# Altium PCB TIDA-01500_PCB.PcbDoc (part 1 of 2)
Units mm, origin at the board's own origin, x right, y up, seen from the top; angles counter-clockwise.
Board outline 177.8 x 50.8 mm, 2 copper layers (Top Layer, Bottom Layer), stack 1.575 mm thick; 57 components, 28 nets, 152 pads, 175 vias.
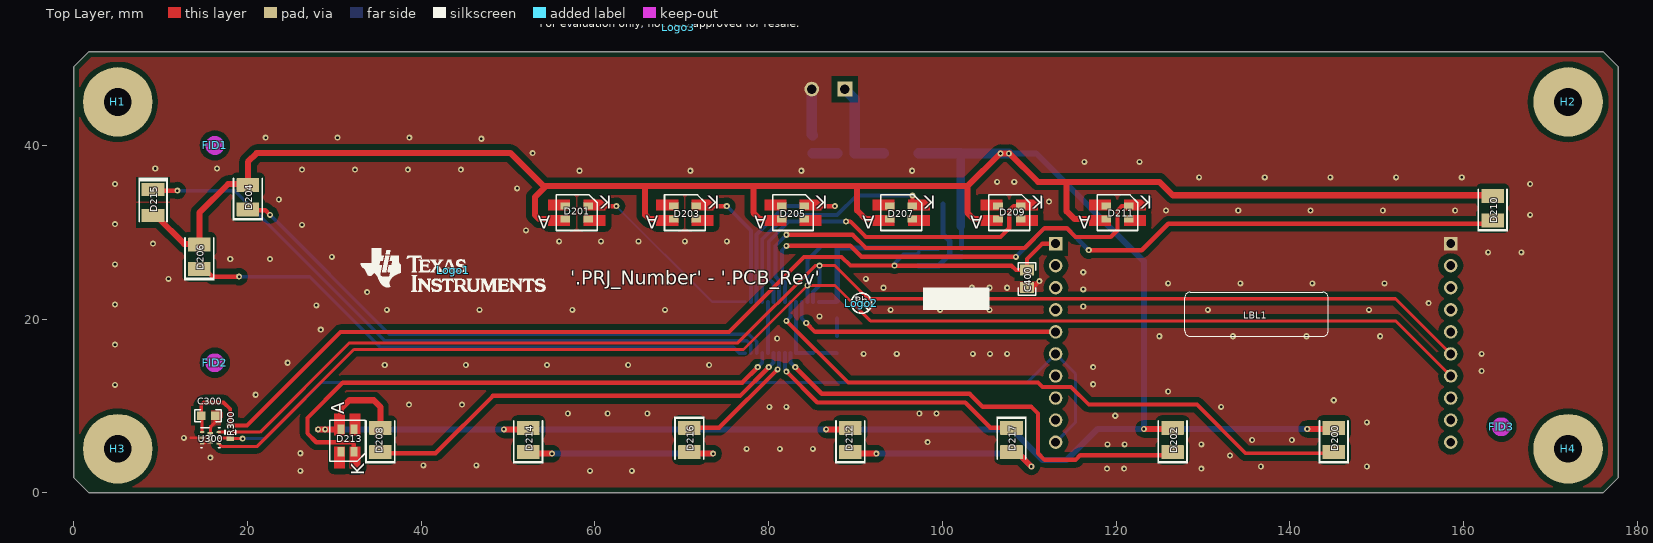
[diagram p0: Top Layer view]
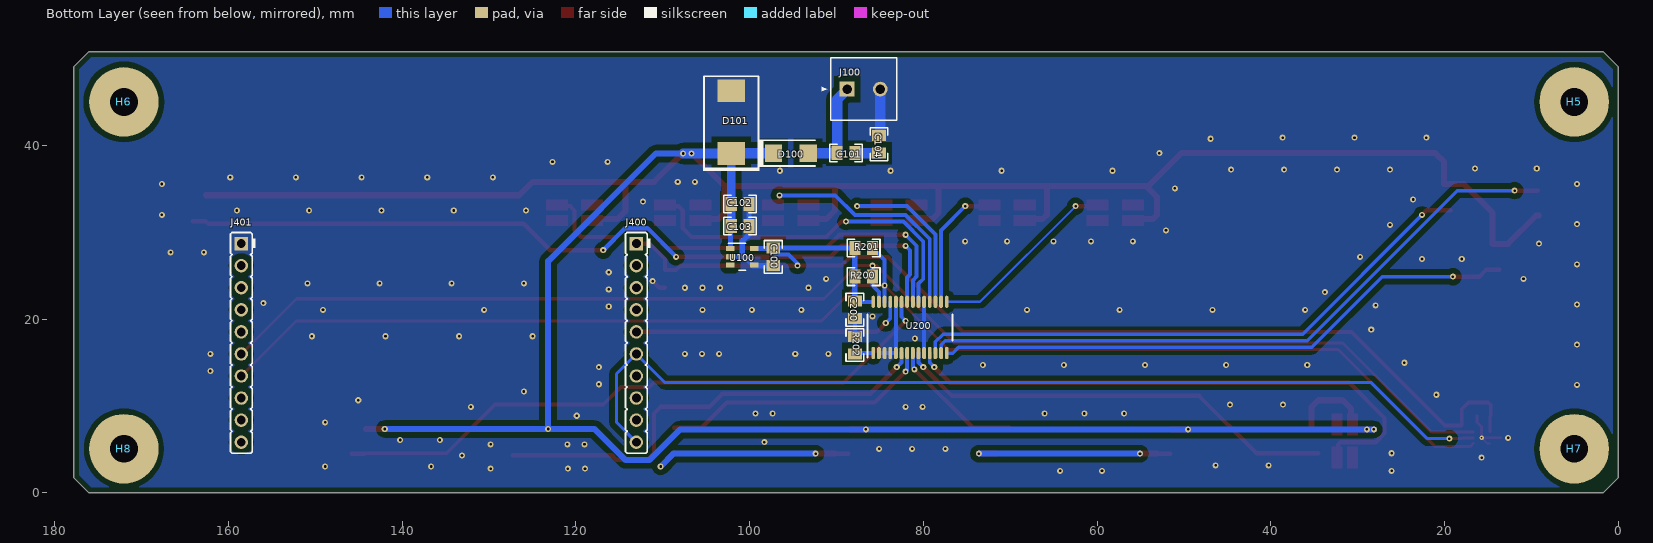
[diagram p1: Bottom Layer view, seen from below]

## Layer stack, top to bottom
Top Solder: solder mask 0.0102, Solder Resist, Dk 3.5
Top Layer: signal copper 0.0356
Dielectric1: core 1.5037, FR-4, Dk 4.8
Bottom Layer: signal copper 0.0356
Bottom Solder: solder mask 0.0102, Solder Resist, Dk 3.5

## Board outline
0,1.778 0,49.022 1.778,50.8 176.022,50.8 177.8,49.022 177.8,1.778 176.022,0 1.778,0

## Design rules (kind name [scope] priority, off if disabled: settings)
AcuteAngle [All] p1: minimum=4.50000000000000E+0001 checktracksonly=FALSE
AssemblyTestPointUsage [All] p1: valid=2
BoardOutlineClearance BoardOutlineClearance_MountingHoles [OnCopper and InComponentClass('Mounting Holes')] p1: gap=1.016 ignorepadtopadclearanceinfootprint=FALSE
BoardOutlineClearance BoardOutlineClearance_Poly [OnCopper and IsPoly] p2: gap=0.635 ignorepadtopadclearanceinfootprint=FALSE
BoardOutlineClearance [OnCopper and Not InComponentClass('Logo') and not InComponentClass('FiducialMark') and not InRegion(1000,500,4000,800) and not InPoly] p3: gap=1.905 ignorepadtopadclearanceinfootprint=FALSE
Clearance Clearance_Keepouts [((IsTrack Or IsArc) And Not InPoly) And IsFree and IsKeepOut vs ((IsTrack Or IsArc) And Not InPoly) And IsFree and IsKeepOut] p1: gap=0 ignorepadtopadclearanceinfootprint=FALSE
Clearance Clearance_Poly [InPolygon] p2: gap=0.635 ignorepadtopadclearanceinfootprint=FALSE except(0: Arc-Hole Track-Hole SMDPad-Hole THPad-Hole Via-Hole Fill-Hole Poly-Hole Region-Hole Text-Hole)
Clearance [All vs not InComponentClass('FiducialMark')] p3: gap=0.2 ignorepadtopadclearanceinfootprint=FALSE except(0: Arc-Hole Track-Hole SMDPad-Hole THPad-Hole Via-Hole Fill-Hole Poly-Hole Region-Hole Text-Hole)
ComponentClearance ComponentClearance_MountingHoles_FiducialMarks [InComponentClass('Mounting Holes') vs InComponentClass('FiducialMark')] p1: gap=1.27 collisioncheckmode=3 verticalgap=0.254 showdistances=FALSE
ComponentClearance ComponentClearance_Shunt [InComponentClass('Header') vs InComponentClass('Shunt')] p2: gap=0 collisioncheckmode=3 verticalgap=0 showdistances=FALSE
ComponentClearance ComponentClearance_Logo [InComponentClass('Logo')] p3: gap=1.27 collisioncheckmode=3 verticalgap=0.254 showdistances=FALSE
ComponentClearance ComponentClearance_ScrewToNut [(HasFootprint('NY PMS 440 0025 PH')) vs (HasFootprint('Keystone_1902C'))] p4: gap=0.127 collisioncheckmode=3 verticalgap=0.254 showdistances=FALSE
ComponentClearance ComponentClearance_MountingHoles [InComponentClass('Mounting Holes')] p5: gap=6.35 collisioncheckmode=3 verticalgap=2540 showdistances=FALSE
ComponentClearance ComponentClearance_SmallPassives [HasFootprint('0201*') or HasFootprint('0402*') or HasFootprint('0508') or HasFootprint('0603*') or HasFootprint('0612') or HasFootprint('0805*') or HasFootprint('0815*') or HasFootprint('0830*') or HasFootprint('1206*') or HasFootprint('1210*') or HasFootprint('1808*') or HasFootprint('1812*') or HasFootprint('1825*') or HasFootprint('2010*') or HasFootprint('2220*') or HasFootprint('2225*') or HasFootprint('2512*') or HasFootprint('2728*') or HasFootprint('3518*') vs HasFootprint('0201*') or HasFootprint('0402*') or HasFootprint('0508') or HasFootprint('0603*') or HasFootprint('0612') or HasFootprint('0805*') or HasFootprint('0815*') or HasFootprint('0830*') or HasFootprint('1206*') or HasFootprint('1210*') or HasFootprint('1808*') or HasFootprint('1812*') or HasFootprint('1825*') or HasFootprint('2010*') or HasFootprint('2220*') or HasFootprint('2225*') or HasFootprint('2512*') or HasFootprint('2728*') or HasFootprint('3518*')] p6: gap=0.38 collisioncheckmode=3 verticalgap=0.254 showdistances=FALSE
ComponentClearance ComponentClearance_THtoSMT [IsThruComponent vs IsSMTComponent] p7: gap=1.016 collisioncheckmode=3 verticalgap=0.762 showdistances=FALSE
ComponentClearance ComponentClearance_THtoTH [IsThruComponent vs IsThruComponent] p8: gap=0.762 collisioncheckmode=3 verticalgap=0.762 showdistances=FALSE
ComponentClearance [All] p9: gap=0.762 collisioncheckmode=3 verticalgap=0.254 showdistances=FALSE
DiffPairsRouting [All] p1: maxlimit=2.54 minlimit=0.254 mostfreqgap=0.254 toplayer_minwidth=0.381 toplayer_maxwidth=0.381 toplayer_prefwidth=0.381 bottomlayer_minwidth=0.381 bottomlayer_maxwidth=0.381 bottomlayer_prefwidth=0.381 maxuncoupledlength=25.4
FabricationTestPointUsage TestPointUsage [All] p1: valid=2 allowmultiple=FALSE
FabricationTestpoint Testpoint [All] p1: side=3 testpointundercomponent=TRUE minsize=1.016 maxsize=2.54 preferedsize=1.524 minholesize=0 maxholesize=1.016 preferedholesize=0.813 testpointgrid=0.025 allowsidetop=TRUE allowsidebottom=TRUE usegrid=TRUE gridtolerance=0
FanoutControl Fanout_LCC [IsLCC] p1: bgadir=Out bgaviamode=Centered fanoutstyle=Auto fanoutdirection=Alternating viagrid=0.025 // Fanout_LCC (Default Rule)
FanoutControl Fanout_BGA [IsBGA] p2: bgadir=Out bgaviamode=Centered fanoutstyle=Auto fanoutdirection=Alternating viagrid=0.025 // Fanout_BGA (Default Rule)
FanoutControl Fanout_Default [All] p4: bgadir=Out bgaviamode=Centered fanoutstyle=Auto fanoutdirection=Alternating viagrid=0.025 // Fanout_Default (Default Rule)
FanoutControl Fanout_Small [(CompPinCount < 5)] p5: bgadir=Out bgaviamode=Centered fanoutstyle=Auto fanoutdirection=OutThenIn viagrid=0.025 // Fanout_Small (Default Rule)
HoleSize [All] p1: absolutevalues=TRUE maxlimit=6.375 minlimit=0.2 maxpercent=80.000 minpercent=20.000
MinimumAnnularRing MinimumAnnularRing_ThermalPadVias [IsVia and InAnyComponent] p1 off: minimumring=0.15
MinimumAnnularRing [All] p2: minimumring=0.15
MinimumSolderMaskSliver MinimumSolderMaskSliver_Logo [InComponentClass('Logo') vs InComponentClass('Logo')] p1 off: minsoldermaskwidth=0.018
MinimumSolderMaskSliver [All] p2 off: minsoldermaskwidth=0.1
PlaneClearance [All] p1: clearance=0.5
PlaneConnect [All] p1: planeconnectstyle=Relief reliefexpansion=0.254 reliefentries=4 reliefconductorwidth=0.254 reliefairgap=0.254
PolygonConnect [All] p1: connectstyle=Direct reliefconductorwidth=0.254 reliefentries=4 polygonreliefangle="90 Angle" airgapwidth=0.254
RoutingVias ThermalPadVias [IsVia and InAnyComponent] p1: holewidth=0.2 width=0.5 viastyle="Through Hole" minholewidth=0.2 minwidth=0.5 maxholewidth=0.4 maxwidth=0.8
RoutingVias [All] p2: holewidth=0.406 width=0.864 viastyle="Through Hole" minholewidth=0.2 minwidth=0.66 maxholewidth=1.016 maxwidth=1.651
ShortCircuit ShortCircuit_1 [HasFootprint('LED_PowerTOPLED_GF')] p1: allowed=TRUE
ShortCircuit [All] p2: allowed=FALSE
SilkToBoardRegionClearance [Not ((IsComment or IsDesignator) And (Hide <> 'False')) and not InRegion(1000,500,4000,800)] p1:
SilkToSilkClearance SilkToSilkClearance_Pb-FreeLogo [(HasFootprint('Pb-Free_Overlay_Medium') OR HasFootprint('Pb-Free_Overlay_Small')) vs (HasFootprint('Pb-Free_Overlay_Medium') OR HasFootprint('Pb-Free_Overlay_Small'))] p1 off: silktosilkclearance=0
SilkToSilkClearance [All] p2 off: silktosilkclearance=0.102
SilkToSolderMaskClearance SilkToComponentPadClearance [(IsPad or IsFill or IsRegion) and InAnycomponent] p1 off: minsilkscreentomaskgap=0.127 clearancetoexposedcopper=TRUE
SilkToSolderMaskClearance "Silk to Solder Mask Opening" [All] p2 off: minsilkscreentomaskgap=0.102 clearancetoexposedcopper=FALSE
SolderMaskExpansion [All] p1: expansion=0.05
Width [All] p1: maxlimit=2.54 minlimit=0.152 preferedwidth=0.254 checkconnectedcopper=TRUE
13 further rules are at their usual default settings.

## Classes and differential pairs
component class TIDA-01500_BlankSheet: C100 C101 C102 C103 C104 C200 C300 C400 D100 D101 D200 D201 D202 D203 D204 D205 D206 D207 D208 D209 D210 D211 D212 D213 D214 D215 D216 D217 J100 J400 J401 R200 R201 R202 R300 U100 U200 U300
component class "Mounting Holes": H1 H2 H3 H4
component class Logo: Logo1
component class TIDA-01500_EVM_Hardware: FID1 FID2 FID3 H1 H2 H3 H4 H5 H6 H7 H8 LBL1 Logo1 Logo2 Logo3 ZZ1 ZZ2 ZZ3 ZZ4
component class FiducialMark: FID1 FID2 FID3
component class AssemblyNote: ZZ1 ZZ2 ZZ3 ZZ4
component class Label: LBL1

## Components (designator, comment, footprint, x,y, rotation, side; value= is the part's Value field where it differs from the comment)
C100 "CGA4J3X7R1H105K125AB" 0805_HV 97.274,27.178 r270 bottom value=1uF
C101 "GCM21BR72A473KA37L" 0805_HV 88.9,39.116 r180 bottom value=0.047uF
C102 "GCM21BR71H104KA37K" 0805_HV 101.092,33.274 r180 bottom value=0.1uF
C103 "CGA4J3X7R1H105K125AB" 0805_HV 101.092,30.734 r180 bottom value=1uF
C104 "GCM21BR72A473KA37L" 0805_HV 85.09,40.132 r90 bottom value=0.047uF
C200 "GCM21BR71H104KA37K" 0805_HV 87.884,21.082 r270 bottom value=0.1uF
C300 "CGJ3E2X7R1C104K080AA" 0603 15.494,8.89 r0 top value=0.1uF
C400 "CGA4J3X7R1H105K125AB" 0805_HV 109.728,24.638 r270 top value=1uF
D100 "B360AM-13-F" SMA 95.25,39.116 r180 bottom value=60V
D101 "TPSMD26A" SMC_265 102.108,42.672 r90 bottom value=26V
D200 "VLMR334BACB-GS08" VLMR334_Red 145.034,6.096 r270 top value=Red
D201 "LW-E6SG" LED_PowerTOPLED_GF 57.912,32.258 r180 top value=White
D202 "VLMR334BACB-GS08" VLMR334_Red 126.492,6.096 r270 top value=Red
D203 "LW-E6SG" LED_PowerTOPLED_GF 70.358,32.258 r180 top value=White
D204 "VLMR334BACB-GS08" VLMR334_Red 20.066,34.036 r270 top value=Red
D205 "LW-E6SG" LED_PowerTOPLED_GF 82.804,32.258 r180 top value=White
D206 "VLMR334BACB-GS08" VLMR334_Red 14.478,27.178 r270 top value=Red
D207 "LW-E6SG" LED_PowerTOPLED_GF 95.25,32.258 r180 top value=White
D208 "VLMR334BACB-GS08" VLMR334_Red 35.306,6.096 r270 top value=Red
D209 "LW-E6SG" LED_PowerTOPLED_GF 107.696,32.258 r180 top value=White
D210 "VLMR334BACB-GS08" VLMR334_Red 163.322,32.766 r270 top value=Red
D211 "LW-E6SG" LED_PowerTOPLED_GF 120.142,32.258 r180 top value=White
D212 "VLMR334BACB-GS08" VLMR334_Red 89.408,6.096 r270 top value=Red
D213 "LY-E6SF" LED_PowerTOPLED_GF 31.52,6.019 r90 top value=Yellow
D214 "VLMR334BACB-GS08" VLMR334_Red 52.324,6.096 r270 top value=Red
D215 "LB T673-L2P1-25-Z" LB_T673_Blue 9.144,33.436 r180 top value=Blue
D216 "VLMR334BACB-GS08" VLMR334_Red 70.866,6.096 r90 top value=Red
D217 "VLMR334BACB-GS08" VLMR334_Red 107.95,6.096 r90 top value=Red
FID1 "Fiducial" Fiducial10-20 16.256,40 r0 top
FID2 "Fiducial" Fiducial10-20 16.256,14.986 r0 top
FID3 "Fiducial" Fiducial10-20 164.338,7.62 r0 top
H1 "NY PMS 440 0025 PH" "NY PMS 440 0025 PH" 5.08,45 r0 top locked
H2 "NY PMS 440 0025 PH" "NY PMS 440 0025 PH" 172,45 r0 top locked
H3 "NY PMS 440 0025 PH" "NY PMS 440 0025 PH" 5.08,5.08 r0 top locked
H4 "NY PMS 440 0025 PH" "NY PMS 440 0025 PH" 172,5.08 r0 top locked
H5 "1902C" Keystone_1902C 5.08,45 r180 bottom locked
H6 "1902C" Keystone_1902C 172,45 r180 bottom locked
H7 "1902C" Keystone_1902C 5.08,5.08 r180 bottom locked
H8 "1902C" Keystone_1902C 172,5.08 r180 bottom locked
J100 "1727010" PhoenixConact_1727010 86.868,46.482 r180 bottom
J400 "SSHQ-110-S-08-G-LF" Major_SSHQ-110-S-08 113.03,17.272 r270 bottom
J401 "SSHQ-110-S-08-G-LF" Major_SSHQ-110-S-08 158.496,17.272 r270 bottom
LBL1 "Size: 0.65\" x 0.20 \"" Label_650x200 136.144,20.574 r0 top
Logo1 "Texas Instruments" TI_Stacked_Overlay_Small 43.688,25.654 r0 top
Logo2 "Pb-Free Symbol" Pb-Free_Overlay_Small 90.678,21.844 r0 top
Logo3 "FCC disclaimer" FCC_disclaimer 69.596,53.594 r0 top
R200 "ERJ-P06F4701V" 0805_HV 86.868,24.892 r0 bottom value=4.70k
R201 "ERJ-P06F4701V" 0805_HV 86.868,28.194 r0 bottom value=4.70k
R202 "ERA-6AEB6650V" 0805_HV 87.884,17.018 r270 bottom value=665
R300 "TNPW060310K0BEEA" TNPW0603 18.034,7 r270 top value=10.0k
U100 "TPS70933QDBVRQ1" DBV0005A_N 100.83,27.178 r180 bottom
U200 "TLC59116IPWRG4" PW0028A_N 81.534,19.05 r90 bottom
U300 "OPT3001DNPR" DNP0006A 15.748,6.35 r0 top
ZZ1 "This Assembly Note is for PCB labels only" AssemblyNoteLabel 4.699,100.025 r0 top
ZZ2 "These assemblies are ESD sensitive, ESD precautions shall be observed." AssemblyNote 4.699,97.259 r0 top
ZZ3 "These assemblies must be clean and free from flux and all contaminants. Use of no clean flux is not acceptable." AssemblyNote 4.699,95.01 r0 top
ZZ4 "These assemblies must comply with workmanship standards IPC-A-610 Class 2, unless otherwise specified." AssemblyNote 4.699,92.761 r0 top

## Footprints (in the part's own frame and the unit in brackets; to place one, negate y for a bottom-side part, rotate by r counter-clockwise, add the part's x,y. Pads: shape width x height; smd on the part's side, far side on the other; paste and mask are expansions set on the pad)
0603 [mm] "0603 from SM-752 data"
  rect 1x0.95 smd: 1(-0.8,0) 2(0.8,0)
  silkscreen extent -1.52,-0.69 1.52,0.69, body extent -0.87,-0.47 0.87,0.47, height 1
0805_HV [mil] "0805 with 30mil clearance between pads"
  rect 50x63 smd: 1(-40,0) 2(40,0)
  silkscreen extent -74,-40 74,40, body extent -43,-29 43,29, height 57
AssemblyNote [mm] "Assembly Note"
AssemblyNoteLabel [mm] "Assembly Note for PCB Labels"
DBV0005A_N [mm] "SOT23, 5-Leads, Body 2.9x1.6mm, Pitch 0.95mm, Lead Span 2.8mm, IPC Medium Density"
  rrect17% 1x0.6 smd: 1(-1.375,0.95) 2(-1.375,0) 3(-1.375,-0.95) 4(1.375,-0.95) 5(1.375,0.95)
  silkscreen extent -1.63,-1.55 0.38,1.55, body extent -1.42,-1.46 1.42,1.46, height 1.09
DNP0006A [mm] "DFN-6 2x2mm"
  oval 0.5x0.25 smd: 1(-0.95,0.65) 2(-0.95,0) 3(-0.95,-0.655) 4(0.95,-0.65) 5(0.95,0) 6(0.95,0.65)
  rect 0.65x1.35 smd paste-0.5: 7(0,0)
  silkscreen extent -1.12,-1.15 1.12,1.15, body extent -1,-1 1,1, height 0.64
FCC_disclaimer [mm]
Fiducial10-20 [mm]
  round 1 smd mask+0.5: 1(0,0)
  Top Layer keep-out circle w1.178: c0,0 r0.5
Keystone_1902C [mil] "Hex Standoff, 4-40 threaded, nylon"
  round 1 on Mech4: 0(0,0)
  body extent -145,-126 146,126, height 501
Label_650x200 [mil] "Thermal Transfer Label"
  round 1 on Mech13: 0(0,0)
  silkscreen extent -325,-100 325,100, body extent -325,-100 325,100, height 1
LB_T673_Blue [mm] "SMD, 2-Leads, Body 3.2x2.8mm"
  rect 2.6x1.5 smd mask+0: 1(0,1.5) 2(0,-1.5)
  silkscreen extent -1.7,-2.9 1.7,2.2, body extent -1.5,-1.85 1.5,1.85, height 2.1
LED_PowerTOPLED_GF [mm] "Osram recommended land pattern,  \"LA_LO_LR_LS_LY_E6SF_Pb_free.pdf\", dated 2008-11-27"
  rect 1.1x0.8 smd: 1(-1.3,0.75) 2(-1.3,-0.75) 3(1.3,-0.75) 4(1.3,0.75)
  silkscreen extent -2.35,-2.05 2.35,2.05, body extent -1.7,-1.5 1.7,1.5, height 2.1
Major_SSHQ-110-S-08 [mm] "Receptacle, 2.54mm, 10x1, TH"
  rect 1.55x1.55 hole 1.02: 1(-11.43,0)
  round 1.55 hole 1.02: 2(-8.89,0) 3(-6.35,0) 4(-3.81,0) 5(-1.27,0) 6(1.27,0) 7(3.81,0) 8(6.35,0) 9(8.89,0) 10(11.43,0)
  silkscreen extent -12.7,-1.24 12.7,1.64, body extent -12.7,-1.24 12.7,1.24, height 8.51
"NY PMS 440 0025 PH" [mm] "4-40 nylon screw and mounting hole"
  round 8 hole 3.2: 1(0,0)
  body extent -3.3,-3.3 3.3,3.3, height 2.69
Pb-Free_Overlay_Small [mm]
  silkscreen extent -1.16,-1.17 1.17,1.17
PhoenixConact_1727010 [mm]
  rect 1.7x1.7 hole 1.1: 1(-1.905,0)
  round 1.7 hole 1.1: 2(1.905,0)
  silkscreen extent -4.8,-3.6 3.81,3.6, body extent -3.81,-3.6 3.81,3.7, height 8.52
PW0028A_N [mm] "TSOP, 28-Leads, Body 9.7x4.4mm, Pitch 0.65mm, IPC Medium Density"
  oval 1.4x0.45 smd: 1(-2.95,4.225) 2(-2.95,3.575) 3(-2.95,2.925) 4(-2.95,2.275) 5(-2.95,1.625) 6(-2.95,0.975) 7(-2.95,0.325) 8(-2.95,-0.325) 9(-2.95,-0.975) 10(-2.95,-1.625) 11(-2.95,-2.275) 12(-2.95,-2.925) 13(-2.95,-3.575) 14(-2.95,-4.225) 15(2.95,-4.225) 16(2.95,-3.575) 17(2.95,-2.925) 18(2.95,-2.275) 19(2.95,-1.625) 20(2.95,-0.975) 21(2.95,-0.325) 22(2.95,0.325) 23(2.95,0.975) 24(2.95,1.625) 25(2.95,2.275) 26(2.95,2.925) 27(2.95,3.575) 28(2.95,4.225)
  silkscreen extent -3.5,-4.9 1.5,4.9, body extent -3.21,-4.85 3.21,4.85, height 1
SMA [mm] "Molded Diode, 2-Leads, Body 4.3x2.6mm, IPC Medium Density, based on OnSemi component dimensions and land pattern"
  rect 2x2 smd: 1(-2,0) 2(2,0)
  silkscreen extent -3.66,-1.57 2.79,1.57, body extent -2.6,-1.3 2.6,1.3, height 2.42
SMC_265 [mm] "SMD, 2-Leads, Body 7.15x6.25mm"
  rect 2.6x3.2 smd: 1(-3.6,0) 2(3.6,0)
  silkscreen extent -5.6,-3.22 5.3,3.22, body extent -4.08,-3.13 4.08,3.13, height 2.65
TI_Stacked_Overlay_Small [mm]
  silkscreen extent -10.63,-2.49 10.63,2.49
TNPW0603 [mm] "Vishay"
  rect 0.5x0.9 smd: 1(-0.75,0) 2(0.75,0)
  silkscreen extent -0.2,-0.6 0.2,0.6, body extent -0.85,-0.47 0.85,0.47, height 0.55
VLMR334_Red [mm] "SMD, 2-Leads, Body 3x2.8mm"
  rrect6% 1.6x2.6 smd: 1(-1.4,0) 2(1.4,0)
  silkscreen extent -2.2,-1.75 2.7,1.75, body extent -1.75,-1.4 1.75,1.4, height 1.65

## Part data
C100 C103 C400: "CAP, CERM, 1 µF, 50 V, +/- 10%, X7R, AEC-Q200 Grade 1, 0805", Cap_Case=0805, Manufacturer=TDK, Supplier Part Number 1=445-6961-1-ND, TempCo=X7R, Tolerance_%=10, Value1="0.008782 ohm", Value2=50V, ValueDisplayed=1µF
C101 C104: "CAP, CERM, 0.047 µF, 100 V, +/- 10%, X7R, AEC-Q200 Grade 1, 0805", Cap_Case=0805, Manufacturer=MuRata, Supplier Part Number 1=490-4969-1-ND, TempCo=X7R, Tolerance_%=10, Value1=Unknown, Value2=100V, ValueDisplayed=0.047µF
C102 C200: "CAP, CERM, 0.1 µF, 50 V, +/- 10%, X7R, AEC-Q200 Grade 1, 0805", Cap_Case=0805, Manufacturer=MuRata, Supplier Part Number 1=490-8049-1-ND, TempCo=X7R, Tolerance_%=10, Value1=Unknown, Value2=50V, ValueDisplayed=0.1µF
C300: "CAP, CERM, 0.1 µF, 16 V,+/- 10%, X7R, AEC-Q200 Grade 1, 0603", Cap_Case=0603, Manufacturer=TDK, Supplier Part Number 1=445-8136-1-ND, TempCo=X7R, Tolerance_%=10, Value2=16V, ValueDisplayed=0.1µF
D100: "Diode, Schottky, 60 V, 3 A, AEC-Q101, SMA", Manufacturer="Diodes Inc.", Supplier Part Number 1=B360AM-13-FDICT-ND, Value1=3A, Value2=0.7V
D101: "Diode, TVS, Uni, 26 V, 42.1 Vc, AEC-Q101, SMC", Manufacturer=Littelfuse, Power_W=6.5, Supplier Part Number 1=F6569CT-ND, Value1=6.5W
D200 D202 D204 D206 D208 D210 D212 D214 D216 D217: "LED, Red, SMD", Color=Red, Manufacturer=Vishay-Semiconductor, Power_TotalModule=0.2, Supplier Part Number 1=VLMR334BACB-GS08CT-ND, Value1=0.2W, Value2=2.2V
D201 D203 D205 D207 D209 D211: "LED, White, SMD", Color=white, ColorTemperature=5600K, Manufacturer=OSRAM, Power_TotalModule=0.102, Supplier Part Number 1=475-1329-1-ND, Value1=0.102W, Value2=3.4V
D213: "LED, Yellow, SMD", Color=yellow, Manufacturer=OSRAM, Power_TotalModule=0.1075, Supplier Part Number 1=475-2791-1-ND, Value1=0.1075W, Value2=2.15V
D215: "LED, Blue, SMD", Color=Blue, Manufacturer=OSRAM, Supplier Part Number 1="LB T673-L2P1-25-Z-ND", Value1=W, Value2=3.1V
FID1 FID2 FID3: "Fiducial mark.  There is nothing to buy or mount.", Manufacturer=N/A
H1 H2 H3 H4: "Machine Screw, Round, #4-40 x 1/4, Nylon, Philips panhead", DigiKeyPartNumber=H542-ND, Manufacturer="B&F Fastener Supply"
H5 H6 H7 H8: "Standoff, Hex, 0.5\"L #4-40 Nylon", Alternate Manufacturer=-, Manufacturer=Keystone, Supplier Part Number 1=1902CK-ND
J100: "Conn Term Block, 2POS, 3.81mm, TH", Manufacturer="Phoenix Contact", Supplier Part Number 1=277-1947-ND
J400 J401: "Receptacle, 2.54mm, 10x1, TH", Color=Black, Current_A=3, Manufacturer="Major League Electronics", Voltage_V=600
LBL1: library part THT-14-423-10, "Thermal Transfer Printable Labels, 0.650\" W x 0.200\" H - 10,000 per roll", Alternate Manufacturer=-, Manufacturer=Brady, Supplier Part Number 1=2065596
Logo1: library part TI_Logo, "Texas Instrument Corporate Signature"
Logo2: library part Pb-Free
Logo3: library part FCC_disclaimer, "FCC_disclaimer"
R200 R201: "RES, 4.70 k, 1%, 0.5 W, AEC-Q200 Grade 0, 0805", Manufacturer=Panasonic, Power_W=0.5, Supplier Part Number 1=P16073CT-ND, TempCo="100 ppm/C", Tolerance_%=1, Value1=1%, Value2=0.5W, Value_Code=4k70, ValueDisplayed=4.70k
R202: "RES, 665, 0.1%, 0.125 W, AEC-Q200 Grade 0, 0805", Manufacturer=Panasonic, Power_W=0.125, Supplier Part Number 1=P665DACT-ND, TempCo="25 ppm/C", Tolerance_%=0.1, Value1=0.1%, Value2=0.125W, Value_Code=665R, ValueDisplayed=665
R300: "RES, 10.0 k, 0.1%, 0.1 W, AEC-Q200 Grade 1, 0603", Manufacturer=Vishay-Dale, Power_W=0.1, Supplier Part Number 1=TNP10.0KAACT-ND, TempCo="25 ppm/C", Value1=0.1%, Value2=0.1W, Value_Code=10k0, ValueDisplayed=10.0k
U100: "150-mA, 30-V, 1-uA IQ Voltage Regulator with Enable, DBV0005A (SOT-23-5)", Alternate Manufacturer="Texas Instruments"
U200: "16-Bit Fast-Mode Plus (FM+) I2C Bus Constant-Current LED Sink Driver, 3 to 5.5 V, -40 to 85 degC, 28-pin SOP (PW28), Green (RoHS & no Sb/Br)", Alternate Manufacturer="Texas Instruments", Alternate PartNumber=Equivalent, Rating=Catalog, Supplier Part Number 1=TLC59116IPWRG4-ND
U300: "Digital Ambient Light Sensor (ALS) with High Precision Human Eye Response, DNP0006A (USON-6)", Alternate Manufacturer="Texas Instruments", Alternate PartNumber=OPT3001DNPT
ZZ1: library part AssemblyNoteLabel, Alternate Manufacturer=-
ZZ2 ZZ3 ZZ4: library part AssemblyNote, Alternate Manufacturer=-

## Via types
v1: diameter 0.7, hole 0.3, Top Layer to Bottom Layer, 174 vias
v2: diameter 0.5, hole 0.2, Top Layer to Bottom Layer, 1 vias

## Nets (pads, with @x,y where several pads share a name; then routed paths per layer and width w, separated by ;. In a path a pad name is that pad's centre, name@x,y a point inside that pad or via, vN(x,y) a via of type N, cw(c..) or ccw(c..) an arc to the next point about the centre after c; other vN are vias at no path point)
12V: C101.1 D100.2 J100.1 | length 11.2
  Bottom Layer w1.2: J100.1@88.773,46.482 89.916,45.339 C101.1@89.916,39.116 D100.2@93.25,39.116
GND: C100.2 C102.2 C103.2 C104.2 C200.2 C300.2 C400.2 D101.2 J100.2 J401.1 R202.1 U100.2 U100.4 U200.2 U200.3 U200.4 U200.5 U200.10 U200.19 U200.24 U300.2 U300.3 U300.7 | length 41
  Top Layer w0.254: 13.462,6.35 U300.2@14.798,6.35 v2(15.748,6.35) 15.093,5.695 U300.3@14.798,5.695
  Top Layer w0.35: v2(15.748,6.35) 15.748,7.62 16.294,8.166 C300.2@16.294,8.89
  Top Layer w0.5: C400.2@109.728,23.622 110.401,23.622 v1(111.163,24.384)
  Bottom Layer w0.45: U200.10@79.909,16.1 U200.19@79.909,22 ; U200.24@83.159,22 U200.5@83.159,16.1 U200.4@83.809,16.1 U200.3@84.459,16.1 U200.2@85.109,16.1 ; R202.1@87.884,18.034 C200.2@87.884,20.066
  Bottom Layer w0.6: C100.2@97.274,26.162 99.568,26.162 100.584,27.178 100.838,27.178 ; C102.2@100.076,33.274 C103.2@100.076,30.734 100.076,29.732 100.838,28.97 100.838,27.178 ; U100.2@102.205,27.178 100.838,27.178
  Bottom Layer w1.2: J100.2@84.963,46.482 84.963,41.275 C104.2@85.09,41.148
  other v1: 26.098,2.54 59.436,2.54 64.262,2.54 118.935,2.794 120.904,2.794 129.794,2.794 136.652,3.048 148.844,3.048 40.259,3.175 46.355,3.175 15.748,4.064 133.096,4.318 26.098,4.572 77.47,5.08 81.28,5.08 85.09,5.08 118.999,5.588 120.968,5.588 129.794,5.588 98.298,5.842 135.636,6.096 140.208,6.096 12.7,6.35 148.844,8.128 119.888,8.89 56.896,9.144 61.468,9.144 66.04,9.144 97.346,9.144 99.314,9.144 80.073,9.906 82.042,9.906 132.08,9.906 38.608,10.16 44.704,10.16 145.034,10.668 20.955,11.303 125.984,11.684 4.763,12.446 117.348,12.509 162.052,14.034 117.348,14.478 35.814,14.732 45.148,14.732 54.483,14.732 63.817,14.732 73.152,14.732 24.638,14.986 90.932,16.002 94.742,16.002 103.505,16.002 105.474,16.002 107.442,16.002 162.052,16.002 4.763,17.069 80.982,17.78 124.968,18.034 133.435,18.034 141.901,18.034 150.368,18.034 28.448,18.796 85.852,20.32 36.05,21.082 46.724,21.082 57.398,21.082 68.072,21.082 94.043,21.082 99.727,21.082 105.41,21.082 130.556,21.082 149.098,21.082 116.205,21.463 27.94,21.59 4.763,21.692 155.956,21.844 33.782,23.114 116.205,23.431 93.218,23.622 103.378,23.622 105.41,23.622 107.442,23.622 125.984,24.13 134.281,24.13 142.579,24.13 150.876,24.13 10.922,24.638 91.186,24.638 116.205,25.4 4.763,26.314 18.034,26.924 22.606,26.924 29.718,27.178 162.814,27.686 166.624,27.686 9.144,28.702 55.88,28.956 60.706,28.956 65.024,28.956 70.358,28.956 75.184,28.956 52.07,30.226 26.289,30.861 4.763,30.937 167.64,32.004 125.73,32.512 134.048,32.512 142.367,32.512 150.685,32.512 159.004,32.512 112.268,33.528 23.622,33.782 51.054,35.052 4.763,35.56 167.64,35.56 106.299,35.814 108.267,35.814 129.54,36.322 137.096,36.322 144.653,36.322 152.209,36.322 159.766,36.322 58.229,37.084 70.993,37.084 83.757,37.084 96.52,37.084 26.289,37.211 32.385,37.211 38.481,37.211 44.577,37.211 9.398,37.338 16.51,37.338 116.332,38.1 122.682,38.1 52.832,39.116 46.926,40.767 22.098,40.894 30.374,40.894 38.65,40.894
INT: J400.6 J400.10 R300.2 U300.5 | length 112.5
  Top Layer w0.35: U300.5@16.698,6.35 17.934,6.35 R300.2@18.034,6.25 v1(19.458,6.25)
  Bottom Layer w0.35: v1(19.458,6.25) 21.998,6.25 28.448,12.7 109.728,12.7 J400.6@113.03,16.002 115.316,13.716 115.316,8.128 J400.10@113.03,5.842
NetC101_2: C101.2 C104.1 | length 2.8
  Bottom Layer w1.2: C104.1@85.09,39.116 C101.2@87.884,39.116
NetD212_2: D212.2 D217.1 | length 24.3
  Top Layer w0.5: D212.2@88.658,4.519 D212.2@90.158,4.519
  Top Layer w0.7: D212.2@90.158,4.519 v1(92.403,4.519) ; D217.1@108.7,4.519 108.765,4.519 v1(110.236,3.048)
  Bottom Layer w0.7: v1(92.403,4.519) 108.765,4.519 v1(110.236,3.048)
NetD214_2: D214.2 D216.1 | length 24
  Top Layer w0.5: D214.2@51.574,4.519 D214.2@53.074,4.519
  Top Layer w0.7: D214.2@53.074,4.519 v1(55.065,4.519) ; D216.1@71.616,4.519 v1(73.607,4.519)
  Bottom Layer w0.7: v1(55.065,4.519) v1(73.607,4.519)
NetR202_2: R202.2 U200.1 | length 2.2
  Bottom Layer w0.254: R202.2@87.786,16.1 R202.2@87.884,16.002
  Bottom Layer w0.45: U200.1@85.759,16.1 R202.2@87.786,16.1
OUT0: D202.2 U200.6 | length 53.4
  Top Layer w0.5: v1(83.058,14.478) 86.106,11.43 103.124,11.43 104.648,9.906 110.236,9.906 110.998,9.144 110.998,4.572 111.76,3.81 115.316,3.81 115.848,4.342 125.742,4.342 D202.2@127.242,4.342
  Bottom Layer w0.45: U200.6@82.509,16.1 82.509,15.027 v1(83.058,14.478)
OUT1: D217.2 U200.7 | length 31.5
  Top Layer w0.5: v1(82.042,13.97) 85.598,10.414 102.616,10.414 105.511,7.519 107.2,7.519 D217.2@108.7,7.519
  Bottom Layer w0.45: U200.7@81.859,16.1 81.859,14.153 v1(82.042,13.97)
OUT2: D216.2 U200.8 | length 15.6
  Top Layer w0.5: D216.2@70.116,7.519 71.616,7.519 74.321,7.519 v1(81.026,14.224)
  Bottom Layer w0.45: v1(81.026,14.224) 81.209,14.407 U200.8@81.209,16.1
OUT3: D208.2 U200.9 | length 51.4
  Top Layer w0.5: D208.2@34.544,4.572 41.656,4.572 48.26,11.176 76.708,11.176 v1(80.01,14.478)
  Bottom Layer w0.45: v1(80.01,14.478) 80.559,15.027 U200.9@80.559,16.1
OUT4: D213.2 U200.11 | length 64.5
  Top Layer w0.5: D213.2@32.258,4.826 32.258,5.588 32.004,5.842 27.94,5.842 26.924,6.858 26.924,8.636 30.988,12.7 76.962,12.7 v1(78.74,14.478)
  Bottom Layer w0.45: v1(78.74,14.478) 79.259,14.997 U200.11@79.259,16.1
OUT5: D204.2 U200.12 | length 66.9
  Top Layer w0.5: D204.2@19.316,32.536 22.074,32.536 v1(22.606,32.004)
  Bottom Layer w0.4: v1(22.606,32.004) 36.322,18.288 77.724,18.288 78.609,17.403 U200.12@78.609,16.1
OUT6: D215.2 U200.13 | length 77.2
  Top Layer w0.254: D215.2@9.144,34.936 D215.2@9.282,34.798
  Top Layer w0.5: D215.2@9.282,34.798 v1(11.938,34.798)
  Bottom Layer w0.4: v1(11.938,34.798) 18.542,34.798 35.814,17.526 77.47,17.526 77.959,17.037 U200.13@77.959,16.1
OUT7: D206.2 U200.14 | length 68.3
  Top Layer w0.5: D206.2@13.728,25.678 D206.2@15.228,25.678 ; D206.2@14.478,25.654 15.24,25.654 16.002,24.892 v1(19.05,24.892)
  Bottom Layer w0.4: v1(19.05,24.892) 27.178,24.892 35.306,16.764 75.946,16.764 76.61,16.1 U200.14@77.309,16.1
OUT8: D201.2 U200.15 | length 22.7
  Top Layer w0.5: D201.2@59.212,33.008 v1(62.472,33.008)
  Bottom Layer w0.254: v1(62.472,33.008) 73.48,22 U200.15@77.309,22
OUT9: D203.2 U200.16 | length 15.7
  Top Layer w0.5: D203.2@71.658,33.008 v1(75.172,33.008)
  Bottom Layer w0.45: v1(75.172,33.008) 77.959,30.221 U200.16@77.959,22
OUT10: D205.2 U200.17 | length 21.6
  Top Layer w0.5: D205.2@84.104,33.008 v1(87.618,33.008)
  Bottom Layer w0.45: U200.17@78.609,22 78.609,29.759 81.858,33.008 v1(87.618,33.008)
OUT11: D207.2 U200.18 | length 27.9
  Top Layer w0.5: D207.2@96.55,33.008 v1(96.55,34.26)
  Bottom Layer w0.45: U200.18@79.259,22 79.259,29.221 82.042,32.004 87.884,32.004 90.14,34.26 v1(96.55,34.26)
OUT12: D209.2 U200.20 | length 40.5
  Top Layer w0.5: v1(88.9,31.242) 89.408,31.242 91.186,29.464 106.68,29.464 107.696,30.48 107.696,32.512 108.192,33.008 D209.2@108.996,33.008
  Bottom Layer w0.45: U200.20@80.559,22 80.559,24.089 80.01,24.638 80.01,28.956 82.296,31.242 v1(88.9,31.242)
OUT13: D211.2 U200.21 | length 52.6
  Top Layer w0.5: v1(82.042,29.718) 89.662,29.718 91.186,28.194 109.474,28.194 111.76,30.48 114.3,30.48 115.316,29.464 119.38,29.464 120.142,30.226 120.142,32.512 120.65,33.02 D211.2@121.412,33.02
  Bottom Layer w0.45: U200.21@81.209,22 81.209,24.455 80.772,24.892 80.772,28.448 v1(82.042,29.718)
